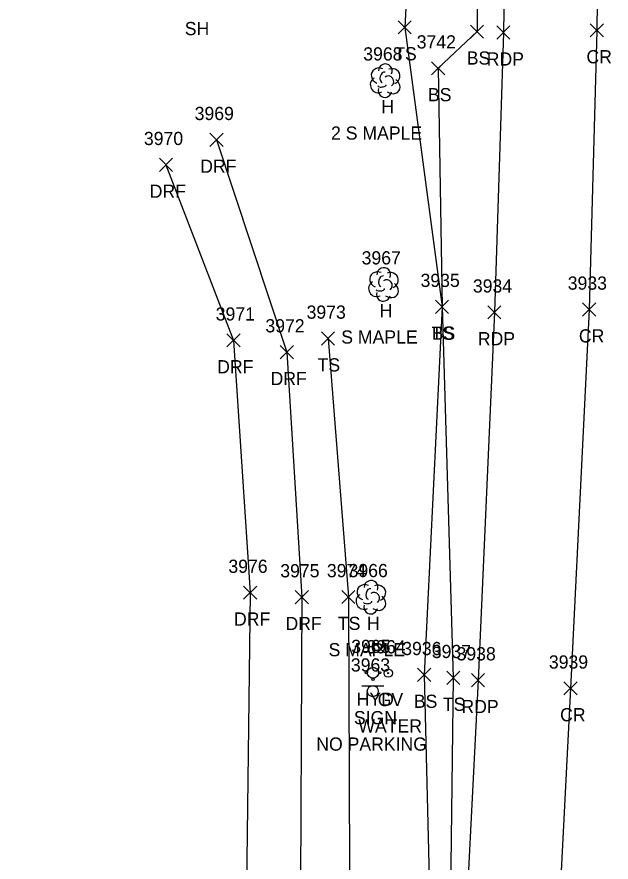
# Model space of a CAD drawing. Extents: x 1678863 to 1683592, y 407783 to 418211.
# Drawn here: x 1680263.1 to 1680353.2, y 413885.1 to 414013.2 of the extents above; entities that cross this region are included whole.
import ezdxf

# ---------------------------------------------------------------- set-up
doc = ezdxf.new("R2010")
doc.units = 0
for name, color, linetype in [('L_A', 7, 'Continuous'), ('L_C', 7, 'Continuous'), ('L_I', 7, 'Continuous'), ('L_TIC', 7, 'Continuous'), ('LELB', 7, 'Continuous'), ('LTD', 7, 'Continuous'), ('P_A', 7, 'Continuous'), ('P_I', 7, 'Continuous'), ('P_TIC', 7, 'Continuous'), ('PET', 7, 'Continuous'), ('PRC', 7, 'Continuous'), ('R_A', 7, 'Continuous'), ('R_I', 7, 'Continuous'), ('R_TIC', 7, 'Continuous'), ('RDF', 7, 'Continuous'), ('S_A', 7, 'Continuous'), ('S_C', 7, 'Continuous'), ('S_I', 7, 'Continuous'), ('SSGN', 7, 'Continuous'), ('U_A', 7, 'Continuous'), ('U_C', 7, 'Continuous'), ('U_I', 7, 'Continuous'), ('UWFH', 7, 'Continuous'), ('UWV', 7, 'Continuous')]:
    doc.layers.add(name, color=color, linetype=linetype)

msp = doc.modelspace()

# ---------------------------------------------------------------- linework, layer by layer
at = {"layer": 'L_TIC'}
for points in [[(1680320.93, 414010.62), (1680322.93, 414012.62)], [(1680322.93, 414010.62), (1680320.93, 414012.62)], [(1680331.9, 414009.98), (1680333.9, 414011.98)], [(1680333.9, 414009.98), (1680331.9, 414011.98)], [(1680326.01, 414004.42), (1680328.01, 414006.42)], [(1680328.01, 414004.42), (1680326.01, 414006.42)], [(1680326.59, 413968.26), (1680328.59, 413970.26)], [(1680328.59, 413968.26), (1680326.59, 413970.26)], [(1680326.59, 413968.26), (1680328.59, 413970.26)], [(1680328.59, 413968.26), (1680326.59, 413970.26)], [(1680309.3, 413963.45), (1680311.3, 413965.45)], [(1680311.3, 413963.45), (1680309.3, 413965.45)], [(1680312.38, 413924.26), (1680314.38, 413926.26)], [(1680314.38, 413924.26), (1680312.38, 413926.26)], [(1680323.87, 413912.45), (1680325.87, 413914.45)], [(1680325.87, 413912.45), (1680323.87, 413914.45)], [(1680328.3, 413912), (1680330.3, 413914)], [(1680330.3, 413912), (1680328.3, 413914)]]:
    msp.add_lwpolyline(points, dxfattribs=at)
at = {"layer": 'LELB'}
for points in [[(1680328.8, 414196.16), (1680329.42, 414154.35), (1680329.9, 414108.73), (1680324.37, 414065.09), (1680323.69, 414045.18), (1680321.93, 414011.62), (1680327.59, 413969.26), (1680329.3, 413913), (1680328.66, 413864.29), (1680326.97, 413811.9), (1680324.77, 413763.09), (1680322.28, 413714.15), (1680319.32, 413666.59), (1680317.19, 413631.47), (1680315.04, 413584.83), (1680311.9, 413541.88), (1680311.77, 413525.72)], [(1680333.49, 414185.64), (1680335.28, 414154.34), (1680335.31, 414108.58), (1680333.17, 414064.14), (1680332.9, 414010.98), (1680327.01, 414005.42), (1680327.59, 413969.26), (1680324.87, 413913.45), (1680326.11, 413864.17), (1680324.22, 413811.96), (1680322.23, 413763.08), (1680318.76, 413714.44), (1680316.65, 413667.05), (1680314.69, 413647.98), (1680313.33, 413619.55), (1680312.59, 413608.22), (1680310.92, 413608.34)], [(1680310.3, 413964.45), (1680313.38, 413925.26), (1680313.62, 413870.17), (1680310.5, 413836.3), (1680310.39, 413783.38), (1680310.23, 413740.98), (1680305.9, 413695.45), (1680302.22, 413648.42), (1680299.26, 413611.53), (1680297.37, 413601.66), (1680307.54, 413597.2), (1680308.18, 413584.58), (1680306.18, 413542.36), (1680304.07, 413518.67), (1680292.7, 413506.12)]]:
    msp.add_lwpolyline(points, dxfattribs=at)
at = {"layer": 'LTD'}
for p, q in [((1680318.94, 414003.6), (1680318.94, 414003.6)), ((1680318.94, 414003.6), (1680318.94, 414003.6)), ((1680318.7, 413972.68), (1680318.7, 413972.68)), ((1680318.7, 413972.68), (1680318.7, 413972.68)), ((1680316.78, 413925.27), (1680316.78, 413925.27)), ((1680316.78, 413925.27), (1680316.78, 413925.27))]:
    msp.add_line(p, q, dxfattribs=at)
for centre in [(1680318.99, 414005.03), (1680318.74, 413974.12), (1680316.82, 413926.71)]:
    msp.add_arc(centre, 1.05, 335.5272, 180.9563, dxfattribs=at)
for centre, major_axis, ratio, start_param, end_param in [((1680318.15, 414004.27), (1.21, -0.51), 0.895232, 1.570796, 4.712389), ((1680318.73, 414004.06), (-0.208, -0.792), 0.645439, 3.141593, 6.283185), ((1680319.98, 414004.18), (-1.14, -0.48), 0.949671, 1.570796, 4.712389), ((1680317.86, 414002.89), (0.58, -1.04), 0.959034, 3.141593, 6.283185), ((1680319.44, 414003.43), (-0.5, 0.667), 0.989748, 3.141593, 6.283185), ((1680319.94, 414002.77), (-1.09, 0.79), 0.841452, 1.570796, 4.712389), ((1680318.94, 414002.1), (0.26, 1.06), 0.942809, 1.570796, 4.712389), ((1680318.49, 414002.85), (-0.625, -0.083), 0.423636, 0, 3.141593), ((1680317.91, 413973.35), (1.21, -0.51), 0.895232, 1.570796, 4.712389), ((1680318.49, 413973.14), (-0.208, -0.792), 0.645439, 3.141593, 6.283185), ((1680319.74, 413973.27), (-1.14, -0.48), 0.949671, 1.570796, 4.712389), ((1680317.61, 413971.98), (0.58, -1.04), 0.959034, 3.141593, 6.283185), ((1680319.2, 413972.52), (-0.5, 0.667), 0.989748, 3.141593, 6.283185), ((1680319.7, 413971.85), (-1.09, 0.79), 0.841452, 1.570796, 4.712389), ((1680318.7, 413971.18), (0.26, 1.06), 0.942809, 1.570796, 4.712389), ((1680318.24, 413971.93), (-0.625, -0.083), 0.423636, 0, 3.141593), ((1680315.98, 413925.94), (1.21, -0.51), 0.895232, 1.570796, 4.712389), ((1680316.57, 413925.73), (-0.208, -0.792), 0.645439, 3.141593, 6.283185), ((1680317.82, 413925.86), (-1.14, -0.48), 0.949671, 1.570796, 4.712389), ((1680315.69, 413924.57), (0.58, -1.04), 0.959034, 3.141593, 6.283185), ((1680317.28, 413925.11), (-0.5, 0.667), 0.989748, 3.141593, 6.283185), ((1680317.78, 413924.44), (-1.09, 0.79), 0.841452, 1.570796, 4.712389), ((1680316.78, 413923.77), (0.26, 1.06), 0.942809, 1.570796, 4.712389), ((1680316.32, 413924.52), (-0.625, -0.083), 0.423636, 0, 3.141593)]:
    msp.add_ellipse(centre, major_axis=major_axis, ratio=ratio, start_param=start_param, end_param=end_param, dxfattribs=at)
at = {"layer": 'P_TIC'}
for points in [[(1680335.89, 414009.83), (1680337.89, 414011.83)], [(1680337.89, 414009.83), (1680335.89, 414011.83)], [(1680350.07, 414010.17), (1680352.07, 414012.17)], [(1680352.07, 414010.17), (1680350.07, 414012.17)], [(1680334.53, 413967.42), (1680336.53, 413969.42)], [(1680336.53, 413967.42), (1680334.53, 413969.42)], [(1680348.92, 413967.85), (1680350.92, 413969.85)], [(1680350.92, 413967.85), (1680348.92, 413969.85)], [(1680332.05, 413911.65), (1680334.05, 413913.65)], [(1680334.05, 413911.65), (1680332.05, 413913.65)], [(1680346.07, 413910.41), (1680348.07, 413912.41)], [(1680348.07, 413910.41), (1680346.07, 413912.41)]]:
    msp.add_lwpolyline(points, dxfattribs=at)
at = {"layer": 'PET'}
msp.add_lwpolyline([(1680337.74, 414063.85), (1680336.89, 414010.83), (1680335.53, 413968.42), (1680333.05, 413912.65), (1680330.57, 413864.02), (1680327.9, 413811.73), (1680326.03, 413762.93), (1680323.35, 413714.16), (1680320.37, 413666.45), (1680318.55, 413631.25), (1680316.14, 413584.69), (1680313.68, 413541.42), (1680312.42, 413523.36), (1680310.1, 413497.18), (1680310.27, 413479.23), (1680309.45, 413465.43), (1680306.28, 413414.4), (1680304.56, 413390.73), (1680303.5, 413367.03), (1680300.17, 413323.12), (1680296.71, 413266.44), (1680294.23, 413226.16), (1680292.89, 413196.25), (1680291.23, 413147.08)], dxfattribs=at)
at = {"layer": 'PRC'}
msp.add_lwpolyline([(1680351.68, 414063.47), (1680351.07, 414011.17), (1680349.92, 413968.85), (1680347.07, 413911.41), (1680344.67, 413863.93), (1680341.49, 413810.97), (1680338.98, 413763.46), (1680336.26, 413713.21), (1680333.88, 413665.73), (1680331.73, 413629.34), (1680329.35, 413585.64), (1680326.79, 413539.67), (1680324.56, 413493.26), (1680322.55, 413462.88), (1680320.16, 413417.83), (1680318.29, 413388.45), (1680316.89, 413365.1), (1680314.19, 413322.55), (1680311.04, 413264.13), (1680308.9, 413226.32), (1680307.27, 413195.54), (1680304.84, 413145.79)], dxfattribs=at)
at = {"layer": 'R_TIC'}
for points in [[(1680292.38, 413993.57), (1680294.38, 413995.57)], [(1680294.38, 413993.57), (1680292.38, 413995.57)], [(1680284.71, 413989.78), (1680286.71, 413991.78)], [(1680286.71, 413989.78), (1680284.71, 413991.78)], [(1680294.95, 413963.17), (1680296.95, 413965.17)], [(1680296.95, 413963.17), (1680294.95, 413965.17)], [(1680303.05, 413961.38), (1680305.05, 413963.38)], [(1680305.05, 413961.38), (1680303.05, 413963.38)], [(1680297.49, 413924.92), (1680299.49, 413926.92)], [(1680299.49, 413924.92), (1680297.49, 413926.92)], [(1680305.31, 413924.24), (1680307.31, 413926.24)], [(1680307.31, 413924.24), (1680305.31, 413926.24)]]:
    msp.add_lwpolyline(points, dxfattribs=at)
at = {"layer": 'RDF'}
for points in [[(1680293.38, 413994.57), (1680304.05, 413962.38), (1680306.31, 413925.24), (1680306.07, 413871.28), (1680307.56, 413836.62), (1680303.79, 413791.26), (1680302.36, 413740.49), (1680301.95, 413696.62), (1680297.83, 413647.55), (1680295.14, 413608.28), (1680287.08, 413579.47)], [(1680285.71, 413990.78), (1680295.95, 413964.17), (1680298.49, 413925.92), (1680297.85, 413873.11), (1680298.81, 413841.35), (1680296.33, 413794.3), (1680294.84, 413741.14), (1680291.28, 413693.58), (1680288.32, 413644.74), (1680285.28, 413613.34), (1680275.4, 413582.62), (1680263.09, 413554.99)]]:
    msp.add_lwpolyline(points, dxfattribs=at)
at = {"layer": 'SSGN'}
for p, q in [((1680315.44, 413911.81), (1680318.77, 413911.81)), ((1680317.09, 413910.98), (1680317.09, 413910.98))]:
    msp.add_line(p, q, dxfattribs=at)
msp.add_circle((1680317.09, 413910.98), 0.833, dxfattribs=at)
at = {"layer": 'UWFH'}
msp.add_line((1680317.12, 413913.77), (1680317.12, 413913.77), dxfattribs=at)
for centre, radius in [((1680316.12, 413913.77), 0.167), ((1680317.12, 413913.77), 0.833), ((1680318.12, 413913.77), 0.167), ((1680317.12, 413912.77), 0.167)]:
    msp.add_circle(centre, radius, dxfattribs=at)
at = {"layer": 'UWV'}
for radius in [0.625, 0.0833]:
    msp.add_circle((1680319.43, 413913.71), radius, dxfattribs=at)

# ---------------------------------------------------------------- texts
at = {"layer": 'L_A'}
for s, p in [('SH', (1680288.56, 414010.44)), ('TS', (1680320.33, 414006.62)), ('BS', (1680331.34, 414005.98)), ('BS', (1680325.45, 414000.42)), ('H', (1680318.38, 413998.6)), ('H', (1680318.13, 413967.68)), ('TS', (1680326, 413964.26)), ('BS', (1680326.03, 413964.26)), ('TS', (1680308.71, 413959.45)), ('TS', (1680311.79, 413920.26)), ('H', (1680316.21, 413920.27)), ('BS', (1680323.31, 413908.45)), ('TS', (1680327.71, 413908))]:
    msp.add_text(s, height=2, dxfattribs=at).set_placement(p)
at = {"layer": 'L_C'}
for s, p in [('2 S MAPLE', (1680310.75, 413994.6)), ('S MAPLE', (1680312.3, 413963.68)), ('S MAPLE', (1680310.38, 413916.27))]:
    msp.add_text(s, height=2, dxfattribs=at).set_placement(p)
at = {"layer": 'L_I'}
for s, p in [('3742', (1680323.75, 414008.42)), ('3968', (1680315.64, 414006.6)), ('3967', (1680315.39, 413975.68)), ('3935', (1680324.33, 413972.26)), ('3935', (1680324.33, 413972.26)), ('3973', (1680307.04, 413967.45)), ('3974', (1680310.12, 413928.26)), ('3966', (1680313.41, 413928.27)), ('3936', (1680321.55, 413916.45)), ('3937', (1680326.04, 413916))]:
    msp.add_text(s, height=2, dxfattribs=at).set_placement(p)
at = {"layer": 'P_A'}
for s, p in [('RDP', (1680334.37, 414005.83)), ('CR', (1680349.5, 414006.17)), ('RDP', (1680333.02, 413963.42)), ('CR', (1680348.35, 413963.85)), ('RDP', (1680330.53, 413907.65)), ('CR', (1680345.5, 413906.41))]:
    msp.add_text(s, height=2, dxfattribs=at).set_placement(p)
at = {"layer": 'P_I'}
for s, p in [('3934', (1680332.27, 413971.42)), ('3933', (1680346.66, 413971.85)), ('3938', (1680329.79, 413915.65)), ('3939', (1680343.8, 413914.41))]:
    msp.add_text(s, height=2, dxfattribs=at).set_placement(p)
at = {"layer": 'R_A'}
for p in [(1680290.91, 413989.57), (1680283.24, 413985.78), (1680293.48, 413959.17), (1680301.58, 413957.38), (1680296.03, 413920.92), (1680303.84, 413920.24)]:
    msp.add_text('DRF', height=2, dxfattribs=at).set_placement(p)
at = {"layer": 'R_I'}
for s, p in [('3969', (1680290.06, 413997.57)), ('3970', (1680282.36, 413993.78)), ('3971', (1680293.26, 413967.17)), ('3972', (1680300.79, 413965.38)), ('3976', (1680295.18, 413928.92)), ('3975', (1680303.05, 413928.24))]:
    msp.add_text(s, height=2, dxfattribs=at).set_placement(p)
at = {"layer": 'S_A'}
msp.add_text('SIGN', height=2, dxfattribs=at).set_placement((1680314.22, 413905.96))
at = {"layer": 'S_C'}
msp.add_text('NO PARKING', height=2, dxfattribs=at).set_placement((1680308.51, 413901.96))
at = {"layer": 'S_I'}
msp.add_text('3963', height=2, dxfattribs=at).set_placement((1680313.76, 413913.96))
at = {"layer": 'U_A'}
for s, p in [('HYD', (1680314.64, 413908.77)), ('GV', (1680317.83, 413908.71))]:
    msp.add_text(s, height=2, dxfattribs=at).set_placement(p)
at = {"layer": 'U_C'}
msp.add_text('WATER', height=2, dxfattribs=at).set_placement((1680314.89, 413904.71))
at = {"layer": 'U_I'}
for s, p in [('3965', (1680313.81, 413916.77)), ('3964', (1680316.12, 413916.71))]:
    msp.add_text(s, height=2, dxfattribs=at).set_placement(p)

doc.saveas('drawing.dxf')
